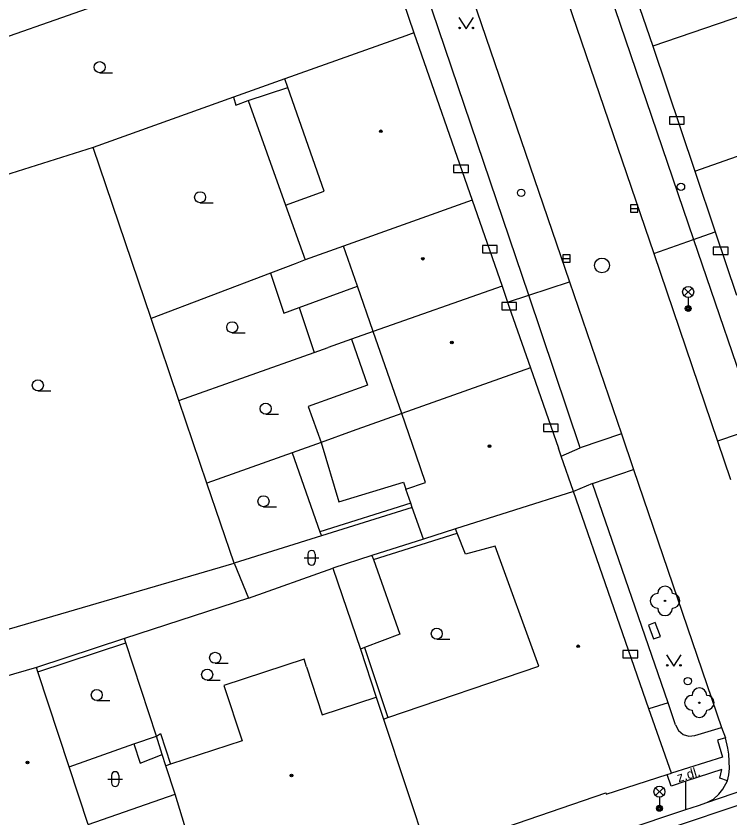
# Model space of a CAD drawing. Extents: x -596229 to -595156, y -1161237 to -1159376.
# Drawn here: x -596026.5 to -595978.1, y -1161185.2 to -1161130.8 of the extents above; entities that cross this region are included whole.
import ezdxf

# ---------------------------------------------------------------- set-up
doc = ezdxf.new("R2010")
doc.units = 0
for name, color, linetype in [('DOP - kresba z DSPS bez souradnic', 7, 'Continuous'), ('DOP - rozhrani ploch obecne', 7, 'Continuous'), ('Level 22', 7, 'Continuous'), ('Level 24', 7, 'Continuous'), ('Level 27', 7, 'Continuous'), ('Level 28', 7, 'Continuous'), ('Level 33', 7, 'Continuous'), ('Level 36', 7, 'Continuous'), ('Level 39', 7, 'Continuous'), ('Specificka linie pasportu komunikaci', 7, 'Continuous'), ('TM - budovy zdene_ betonove - VP', 7, 'Continuous'), ('TM - chodniky - VP', 7, 'Continuous'), ('TM - komunikace - VP', 7, 'Continuous'), ('TM - letecke snimky - pomocna linie', 7, 'Continuous'), ('TM - plot zdeny_ ohradni zed - VP', 7, 'Continuous'), ('TM - popis povrchu', 7, 'Continuous'), ('TM - rozhrani ploch obecne - VP', 7, 'Continuous')]:
    doc.layers.add(name, color=color, linetype=linetype)

msp = doc.modelspace()

# ---------------------------------------------------------------- linework, layer by layer
at = {"layer": 'DOP - kresba z DSPS bez souradnic'}
for points in [[(-596010.78, -1161136.54), (-596008.07, -1161135.66)], [(-595999.73, -1161163.85), (-596005.9, -1161165.79)], [(-596002.27, -1161167.67), (-595996.58, -1161165.87)], [(-596002.37, -1161167.39), (-596002.27, -1161167.67)], [(-596002.27, -1161167.67), (-596000.48, -1161172.72)], [(-596000.48, -1161172.72), (-596002.87, -1161173.64)], [(-596025.04, -1161175.28), (-596019.06, -1161173.32)], [(-596002.87, -1161173.64), (-596003.15, -1161173.74)], [(-596002.87, -1161173.64), (-596001.3, -1161178.39)], [(-596017, -1161179.64), (-596016.71, -1161179.47)], [(-596016.71, -1161179.47), (-596016.04, -1161181.55)], [(-596018.52, -1161180.17), (-596018.09, -1161181.47)], [(-596018.09, -1161181.47), (-596016.6, -1161180.88)]]:
    msp.add_lwpolyline(points, dxfattribs=at)
at = {"layer": 'DOP - rozhrani ploch obecne'}
for points in [[(-596033.56, -1161134.46), (-596017.29, -1161128.73)], [(-596008.28, -1161135.06), (-596011.76, -1161136.3)], [(-596011.76, -1161136.3), (-596021.29, -1161139.72)], [(-596011.76, -1161136.3), (-596011.6, -1161136.84)], [(-596011.6, -1161136.84), (-596010.78, -1161136.54)], [(-596010.78, -1161136.54), (-596008.23, -1161143.62)], [(-596021.29, -1161139.72), (-596030.77, -1161142.7)], [(-596017.35, -1161151.32), (-596021.29, -1161139.72)], [(-596007.57, -1161147.6), (-596008.23, -1161147.85)], [(-596006.89, -1161147.34), (-596007.57, -1161147.6)], [(-596009.26, -1161148.24), (-596017.35, -1161151.32)], [(-596008.23, -1161147.85), (-596009.26, -1161148.24)], [(-596007.31, -1161150.57), (-596006.28, -1161153.62)], [(-596015.47, -1161156.88), (-596017.35, -1161151.32)], [(-596002.28, -1161152.21), (-596003.75, -1161152.73)], [(-596003.75, -1161152.73), (-596005.35, -1161153.29)], [(-596015.47, -1161156.88), (-596006.28, -1161153.62)], [(-596006.28, -1161153.62), (-596005.35, -1161153.29)], [(-596013.57, -1161162.48), (-596015.47, -1161156.88)], [(-596000.35, -1161157.77), (-596003.72, -1161158.97)], [(-596003.72, -1161158.97), (-596005.82, -1161159.72)], [(-596005.82, -1161159.72), (-596007.78, -1161160.42)], [(-596007.78, -1161160.42), (-596013.57, -1161162.48)], [(-596007.78, -1161160.42), (-596005.9, -1161165.79)], [(-596011.73, -1161167.92), (-596013.57, -1161162.48)], [(-595999.63, -1161164.13), (-596005.8, -1161166.07)], [(-596005.8, -1161166.07), (-596011.73, -1161167.92)], [(-596005.9, -1161165.79), (-596005.8, -1161166.07)], [(-595998.88, -1161166.28), (-596002.37, -1161167.39)], [(-596002.37, -1161167.39), (-596005.02, -1161168.25)], [(-596032.32, -1161173.93), (-596011.73, -1161167.92)], [(-596011.73, -1161167.92), (-596010.75, -1161170.28)], [(-596010.75, -1161170.28), (-596005.02, -1161168.25)], [(-596005.02, -1161168.25), (-596003.15, -1161173.74)], [(-596010.75, -1161170.28), (-596019.15, -1161173.03)], [(-596019.15, -1161173.03), (-596025.13, -1161174.99)], [(-596019.06, -1161173.32), (-596019.15, -1161173.03)], [(-596017, -1161179.64), (-596019.06, -1161173.32)], [(-596003.15, -1161173.74), (-596002.08, -1161177)], [(-596018.52, -1161180.17), (-596017, -1161179.64)], [(-596016.6, -1161180.88), (-596017, -1161179.64)], [(-596022.92, -1161181.72), (-596018.52, -1161180.17)], [(-596016.35, -1161181.65), (-596016.6, -1161180.88)]]:
    msp.add_lwpolyline(points, dxfattribs=at)
at = {"layer": 'Level 22'}
for centre in [(-595982.48, -1161170.47), (-595980.15, -1161177.38)]:
    msp.add_circle(centre, 0.05, dxfattribs=at)
for centre, start, end in [((-595982.98, -1161170.47), 90, 270), ((-595982.48, -1161169.97), 0, 180), ((-595981.98, -1161170.47), 270, 90), ((-595982.48, -1161170.97), 180, 0), ((-595980.15, -1161176.88), 0, 180), ((-595980.65, -1161177.38), 90, 270), ((-595979.65, -1161177.38), 270, 90), ((-595980.15, -1161177.88), 180, 0)]:
    msp.add_arc(centre, 0.5, start, end, dxfattribs=at)
at = {"layer": 'Level 24'}
for points in [[(-595982.188, -1161138.129), (-595981.188, -1161138.129), (-595981.188, -1161137.629), (-595982.188, -1161137.629)], [(-595996.828, -1161141.409), (-595995.828, -1161141.409), (-595995.828, -1161140.909), (-595996.828, -1161140.909)], [(-595994.878, -1161146.869), (-595993.878, -1161146.869), (-595993.878, -1161146.369), (-595994.878, -1161146.369)], [(-595979.208, -1161146.979), (-595978.208, -1161146.979), (-595978.208, -1161146.479), (-595979.208, -1161146.479)], [(-595993.558, -1161150.739), (-595992.558, -1161150.739), (-595992.558, -1161150.239), (-595993.558, -1161150.239)], [(-595990.728, -1161158.979), (-595989.728, -1161158.979), (-595989.728, -1161158.479), (-595990.728, -1161158.479)], [(-595983.612, -1161172.122), (-595983.255, -1161173.056), (-595982.788, -1161172.878), (-595983.145, -1161171.944)], [(-595985.338, -1161174.339), (-595984.338, -1161174.339), (-595984.338, -1161173.839), (-595985.338, -1161173.839)]]:
    msp.add_lwpolyline(points, close=True, dxfattribs=at)
at = {"layer": 'Level 27'}
for p, q in [((-595984.82, -1161143.86), (-595984.32, -1161143.86)), ((-595989.42, -1161147.24), (-595988.92, -1161147.24))]:
    msp.add_line(p, q, dxfattribs=at)
for points in [[(-595984.82, -1161144.11), (-595984.32, -1161144.11), (-595984.32, -1161143.61), (-595984.82, -1161143.61)], [(-595989.42, -1161147.49), (-595988.92, -1161147.49), (-595988.92, -1161146.99), (-595989.42, -1161146.99)]]:
    msp.add_lwpolyline(points, close=True, dxfattribs=at)
msp.add_circle((-595986.76, -1161147.72), 0.5, dxfattribs=at)
at = {"layer": 'Level 28'}
for centre in [(-595981.4, -1161142.39), (-595992.24, -1161142.79), (-595980.93, -1161175.91)]:
    msp.add_circle(centre, 0.25, dxfattribs=at)
at = {"layer": 'Level 33'}
for p, q in [((-595981.175, -1161149.78), (-595980.645, -1161149.25)), ((-595981.175, -1161149.25), (-595980.645, -1161149.78)), ((-595980.91, -1161149.89), (-595980.91, -1161150.64)), ((-595983.125, -1161183.68), (-595982.595, -1161183.15)), ((-595983.125, -1161183.15), (-595982.595, -1161183.68)), ((-595982.86, -1161183.79), (-595982.86, -1161184.54))]:
    msp.add_line(p, q, dxfattribs=at)
for centre, radius in [((-595980.91, -1161149.515), 0.375), ((-595980.91, -1161150.64), 0.2), ((-595980.91, -1161150.64), 0.145), ((-595980.91, -1161150.64), 0.0876), ((-595982.86, -1161183.415), 0.375), ((-595982.86, -1161184.54), 0.2), ((-595982.86, -1161184.54), 0.145), ((-595982.86, -1161184.54), 0.0876)]:
    msp.add_circle(centre, radius, dxfattribs=at)
at = {"layer": 'Level 36'}
for p, q in [((-596020.84, -1161134.645), (-596019.965, -1161134.645)), ((-596014.03, -1161143.465), (-596013.155, -1161143.465)), ((-596011.85, -1161152.285), (-596010.975, -1161152.285)), ((-596025.04, -1161156.225), (-596024.165, -1161156.225)), ((-596009.58, -1161157.805), (-596008.705, -1161157.805)), ((-596009.73, -1161164.085), (-596008.855, -1161164.085)), ((-596006.966, -1161167.556), (-596005.966, -1161167.556)), ((-596006.716, -1161167.306), (-596006.716, -1161167.806)), ((-596006.216, -1161167.306), (-596006.216, -1161167.806)), ((-595997.97, -1161173.075), (-595997.095, -1161173.075)), ((-596013.01, -1161174.705), (-596012.135, -1161174.705)), ((-596013.55, -1161175.845), (-596012.675, -1161175.845)), ((-596021.04, -1161177.225), (-596020.165, -1161177.225)), ((-596020.046, -1161182.306), (-596020.046, -1161182.806)), ((-596019.546, -1161182.306), (-596019.546, -1161182.806)), ((-596020.296, -1161182.556), (-596019.296, -1161182.556))]:
    msp.add_line(p, q, dxfattribs=at)
for points in [[(-595996.47, -1161130.91), (-595995.97, -1161131.66), (-595995.47, -1161130.91)], [(-595982.38, -1161174.14), (-595981.88, -1161174.89), (-595981.38, -1161174.14)]]:
    msp.add_lwpolyline(points, dxfattribs=at)
for centre, radius in [((-595996.42, -1161131.61), 0.05), ((-595995.521, -1161131.61), 0.05), ((-596020.84, -1161134.27), 0.375), ((-596014.03, -1161143.09), 0.375), ((-596011.85, -1161151.91), 0.375), ((-596025.04, -1161155.85), 0.375), ((-596009.58, -1161157.43), 0.375), ((-596009.73, -1161163.71), 0.375), ((-595997.97, -1161172.7), 0.375), ((-596013.01, -1161174.33), 0.375), ((-595982.33, -1161174.84), 0.05), ((-595981.431, -1161174.84), 0.05), ((-596013.55, -1161175.47), 0.375), ((-596021.04, -1161176.85), 0.375)]:
    msp.add_circle(centre, radius, dxfattribs=at)
for centre, start, end in [((-596006.466, -1161167.306), 0, 180), ((-596006.466, -1161167.806), 180, 0), ((-596019.796, -1161182.306), 0, 180), ((-596019.796, -1161182.806), 180, 0)]:
    msp.add_arc(centre, 0.25, start, end, dxfattribs=at)
at = {"layer": 'Level 39'}
for centre, radius in [((-596001.76, -1161138.62), 0.09), ((-596001.76, -1161138.62), 0.0398), ((-595998.92, -1161147.26), 0.09), ((-595998.92, -1161147.26), 0.0398), ((-595996.95, -1161152.94), 0.09), ((-595996.95, -1161152.94), 0.0398), ((-595994.39, -1161159.97), 0.09), ((-595994.39, -1161159.97), 0.0398), ((-595988.37, -1161173.55), 0.09), ((-595988.37, -1161173.55), 0.0398), ((-596025.74, -1161181.43), 0.09), ((-596025.74, -1161181.43), 0.0398), ((-596007.83, -1161182.32), 0.09), ((-596007.83, -1161182.32), 0.0398)]:
    msp.add_circle(centre, radius, dxfattribs=at)
at = {"layer": 'Specificka linie pasportu komunikaci'}
for points in [[(-595980.54, -1161145.96), (-595979.08, -1161145.44)], [(-595983.25, -1161146.92), (-595980.54, -1161145.96)], [(-595991.73, -1161149.74), (-595988.97, -1161148.82)], [(-595993.16, -1161150.22), (-595991.73, -1161149.74)], [(-595989.53, -1161160.66), (-595988.23, -1161160.08)], [(-595987.4, -1161162.5), (-595988.69, -1161163.06)], [(-595979.65, -1161184.14), (-595969.78, -1161180.78)], [(-595981.06, -1161184.63), (-595981.06, -1161182.71)]]:
    msp.add_lwpolyline(points, dxfattribs=at)
at = {"layer": 'TM - budovy zdene_ betonove - VP'}
for points in [[(-595985.32, -1161126.99), (-595983.32, -1161132.85)], [(-595974.5, -1161129.83), (-595983.32, -1161132.85)], [(-596000.08, -1161132.14), (-596008.28, -1161135.06)], [(-595999.52, -1161131.94), (-596000.08, -1161132.14)], [(-595999.52, -1161131.94), (-595995.57, -1161143.29)], [(-595983.32, -1161132.85), (-595980.47, -1161141.32)], [(-596008.07, -1161135.66), (-596008.28, -1161135.06)], [(-596005.61, -1161142.68), (-596008.07, -1161135.66)], [(-595980.47, -1161141.32), (-595971.53, -1161138.19)], [(-595980.47, -1161141.32), (-595979.08, -1161145.44)], [(-596008.23, -1161143.62), (-596005.61, -1161142.68)], [(-595995.57, -1161143.29), (-596004.29, -1161146.41)], [(-595995.57, -1161143.29), (-595993.54, -1161149.12)], [(-596008.23, -1161143.62), (-596006.89, -1161147.34)], [(-595979.08, -1161145.44), (-595977.63, -1161149.74)], [(-596004.29, -1161146.41), (-596006.89, -1161147.34)], [(-596003.35, -1161149.13), (-596004.29, -1161146.41)], [(-596002.28, -1161152.21), (-596003.35, -1161149.13)], [(-595993.54, -1161149.12), (-596002.28, -1161152.21)], [(-595993.54, -1161149.12), (-595993.16, -1161150.22)], [(-595993.16, -1161150.22), (-595993.07, -1161150.49), (-595991.62, -1161154.66)], [(-596000.35, -1161157.77), (-596002.28, -1161152.21)], [(-595991.62, -1161154.66), (-596000.35, -1161157.77)], [(-595991.62, -1161154.66), (-595989.72, -1161160.12)], [(-595999.38, -1161160.58), (-596000.35, -1161157.77)], [(-595989.53, -1161160.66), (-595989.72, -1161160.12)], [(-595998.73, -1161162.45), (-595999.38, -1161160.58)], [(-595988.69, -1161163.06), (-595989.53, -1161160.66)], [(-596000.06, -1161162.89), (-595998.73, -1161162.45)], [(-595999.73, -1161163.85), (-596000.06, -1161162.89)], [(-595988.69, -1161163.06), (-595996.69, -1161165.59)], [(-595983.57, -1161177.79), (-595988.69, -1161163.06)], [(-595999.63, -1161164.13), (-595999.73, -1161163.85)], [(-595998.88, -1161166.28), (-595999.63, -1161164.13)], [(-595996.69, -1161165.59), (-595998.88, -1161166.28)], [(-595996.58, -1161165.87), (-595996.69, -1161165.59)], [(-595996.03, -1161167.31), (-595996.58, -1161165.87)], [(-595994.01, -1161166.77), (-595996.03, -1161167.31)], [(-595991.05, -1161174.91), (-595994.01, -1161166.77)], [(-596006.98, -1161174.43), (-596012.41, -1161176.2)], [(-596006.81, -1161174.94), (-596006.98, -1161174.43)], [(-596025.13, -1161174.99), (-596030.37, -1161176.51)], [(-596025.04, -1161175.28), (-596025.13, -1161174.99)], [(-596022.92, -1161181.72), (-596025.04, -1161175.28)], [(-596006.81, -1161174.94), (-596005.75, -1161178.2)], [(-596001.3, -1161178.39), (-595991.05, -1161174.91)], [(-596012.41, -1161176.2), (-596011.18, -1161179.97)], [(-596005.75, -1161178.2), (-596002.08, -1161177)], [(-596002.08, -1161177), (-596001.58, -1161178.49)], [(-595982.05, -1161182.15), (-595983.57, -1161177.79)], [(-596001.58, -1161178.49), (-596001.3, -1161178.39)], [(-596001.58, -1161178.49), (-595998.56, -1161187.63)], [(-596011.18, -1161179.97), (-596016.04, -1161181.55)], [(-596021.63, -1161185.63), (-596022.92, -1161181.72)], [(-596016.04, -1161181.55), (-596016.35, -1161181.65)], [(-596015.73, -1161183.57), (-596016.35, -1161181.65)], [(-595986.47, -1161183.57), (-595982.34, -1161182.24)], [(-595982.34, -1161182.24), (-595982.05, -1161182.15)], [(-596021.63, -1161185.63), (-596015.73, -1161183.57)], [(-596012.97, -1161192.65), (-596015.73, -1161183.57)], [(-595998.56, -1161187.63), (-595986.5, -1161183.48)], [(-595986.5, -1161183.48), (-595986.47, -1161183.57)]]:
    msp.add_lwpolyline(points, dxfattribs=at)
at = {"layer": 'TM - chodniky - VP'}
for points in [[(-595991.73, -1161149.74), (-596006.15, -1161107.19)], [(-595986.96, -1161127.14), (-595980.54, -1161145.96)], [(-595980.54, -1161145.96), (-595976.19, -1161158.7)], [(-595988.23, -1161160.08), (-595991.73, -1161149.74)], [(-595976.19, -1161158.7), (-595978.92, -1161159.63)], [(-595985.44, -1161159.13), (-595988.23, -1161160.08)], [(-595987.4, -1161162.5), (-595984.62, -1161161.55)], [(-595982.28, -1161177.39), (-595987.4, -1161162.5)], [(-595981.77, -1161178.87), (-595982.28, -1161177.39)], [(-595981.77, -1161178.87), (-595981.57, -1161179.26), (-595981.26, -1161179.53), (-595980.86, -1161179.64), (-595980.45, -1161179.61)], [(-595980.45, -1161179.61), (-595978.64, -1161179.05)]]:
    msp.add_lwpolyline(points, dxfattribs=at)
at = {"layer": 'TM - komunikace - VP'}
for points in [[(-596003.02, -1161107.74), (-595988.97, -1161148.82)], [(-595989.7, -1161127.97), (-595983.25, -1161146.92)], [(-595983.25, -1161146.92), (-595978.92, -1161159.63)], [(-595988.97, -1161148.82), (-595985.44, -1161159.13)], [(-595985.44, -1161159.13), (-595984.62, -1161161.55)], [(-595978.92, -1161159.63), (-595978.04, -1161162.24)], [(-595984.62, -1161161.55), (-595978.64, -1161179.05)], [(-595978.64, -1161179.05), (-595978.38, -1161179.75)], [(-595978.25, -1161182.68), (-595978.16, -1161182.27), (-595978.11, -1161181.83), (-595978.15, -1161180.87), (-595978.21, -1161180.46), (-595978.38, -1161179.75)], [(-595979.65, -1161184.14), (-595979.2, -1161183.91), (-595978.82, -1161183.57), (-595978.57, -1161183.25), (-595978.25, -1161182.68)], [(-595980.2, -1161184.34), (-595979.65, -1161184.14)], [(-596041.07, -1161204.75), (-596034.62, -1161202.56), (-596019.88, -1161197.62), (-595981.06, -1161184.63)], [(-595981.06, -1161184.63), (-595980.2, -1161184.34)]]:
    msp.add_lwpolyline(points, dxfattribs=at)
at = {"layer": 'TM - letecke snimky - pomocna linie'}
for points in [[(-596009.26, -1161148.24), (-596008.35, -1161150.95), (-596007.31, -1161150.57)], [(-596007.31, -1161150.57), (-596003.35, -1161149.13)], [(-596003.75, -1161152.73), (-596002.68, -1161155.83), (-596006.7, -1161157.29), (-596005.82, -1161159.72)], [(-596005.82, -1161159.72), (-596004.61, -1161163.75), (-596000.23, -1161162.43), (-596000.06, -1161162.89)], [(-596114.37, -1161230.84), (-596110.09, -1161230.02), (-596106.3, -1161229.01), (-596101.55, -1161227.51), (-596075.04, -1161217.54), (-596057.03, -1161211.03), (-596047.06, -1161207.64), (-596033.59, -1161203.11), (-596007.84, -1161194.47), (-595994.17, -1161189.91), (-595974.75, -1161183.41), (-595950.17, -1161175.18), (-595940.94, -1161172.12)]]:
    msp.add_lwpolyline(points, dxfattribs=at)
at = {"layer": 'TM - plot zdeny_ ohradni zed - VP'}
msp.add_lwpolyline([(-596002.41, -1161123.49), (-595999.52, -1161131.94)], dxfattribs=at)
at = {"layer": 'TM - rozhrani ploch obecne - VP'}
for points in [[(-595982.28, -1161177.39), (-595983.57, -1161177.79)], [(-595978.38, -1161179.75), (-595978.92, -1161179.91), (-595978.59, -1161181.07), (-595982.05, -1161182.15)], [(-595978.25, -1161182.68), (-595978.77, -1161182.49), (-595978.62, -1161181.91), (-595981.06, -1161182.71)], [(-595981.06, -1161182.71), (-595982.06, -1161183.04), (-595982.34, -1161182.24)]]:
    msp.add_lwpolyline(points, dxfattribs=at)

# ---------------------------------------------------------------- texts
at = {"layer": 'TM - popis povrchu'}
msp.add_text('z.dl.', height=0.65, rotation=16.63, dxfattribs=at).set_placement((-595981.56, -1161182.78))

doc.saveas('drawing.dxf')
